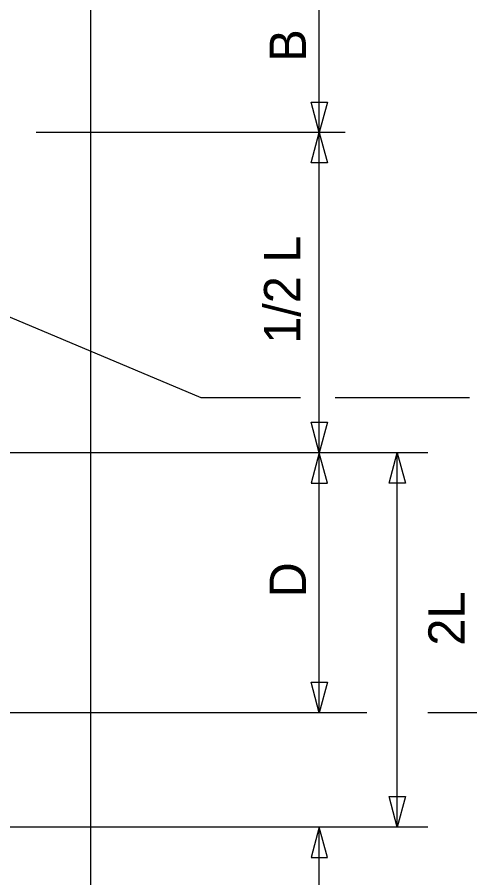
# Model space of a CAD drawing. Extents: x 16038 to 19504, y 5920 to 8321.
# Drawn here: x 17156.2 to 17243.3, y 7550.9 to 7716.4 of the extents above; entities that cross this region are included whole.
import ezdxf

# ---------------------------------------------------------------- set-up
doc = ezdxf.new("R2010")
doc.units = 0
doc.layers.add('PAVT_EDGE_EX', color=7, linetype='Continuous')
doc.layers.add('TYPICAL_TEXT_DIMEN_PR', color=7, linetype='Continuous')

msp = doc.modelspace()

# ---------------------------------------------------------------- linework, layer by layer
at = {"layer": 'PAVT_EDGE_EX'}
msp.add_line((17170.3, 8211.37), (17170.3, 7379.53), dxfattribs=at)
at = {"layer": 'TYPICAL_TEXT_DIMEN_PR'}
for p, q in [((17214.3, 7694.22), (17214.3, 7722.28)), ((17214.3, 7694.22), (17212.73, 7700.08)), ((17212.73, 7700.08), (17214.3, 7700.08)), ((17214.3, 7700.08), (17215.87, 7700.08)), ((17215.87, 7700.08), (17214.3, 7694.22)), ((17219.3, 7694.22), (17159.8, 7694.22)), ((17212.73, 7688.36), (17214.3, 7694.22)), ((17214.3, 7694.22), (17215.87, 7688.36)), ((17214.3, 7632.61), (17214.3, 7694.22)), ((17214.3, 7688.36), (17212.73, 7688.36)), ((17215.87, 7688.36), (17214.3, 7688.36)), ((17126.23, 7670.7), (17191.54, 7643.22)), ((17191.54, 7643.22), (17210.7, 7643.22)), ((17217.38, 7643.22), (17243.22, 7643.22)), ((17214.3, 7632.61), (17212.73, 7638.47)), ((17212.73, 7638.47), (17214.3, 7638.47)), ((17214.3, 7638.47), (17215.87, 7638.47)), ((17215.87, 7638.47), (17214.3, 7632.61)), ((17235.2, 7632.61), (17113.91, 7632.61)), ((17214.3, 7632.61), (17212.73, 7626.75)), ((17215.87, 7626.75), (17214.3, 7632.61)), ((17214.3, 7582.61), (17214.3, 7632.61)), ((17227.73, 7626.75), (17229.3, 7632.61)), ((17229.3, 7560.61), (17229.3, 7632.61)), ((17229.3, 7632.61), (17230.87, 7626.75)), ((17212.73, 7626.75), (17214.3, 7626.75)), ((17214.3, 7626.75), (17215.87, 7626.75)), ((17229.3, 7626.75), (17227.73, 7626.75)), ((17230.87, 7626.75), (17229.3, 7626.75)), ((17214.3, 7582.61), (17212.73, 7588.47)), ((17212.73, 7588.47), (17214.3, 7588.47)), ((17214.3, 7588.47), (17215.87, 7588.47)), ((17215.87, 7588.47), (17214.3, 7582.61)), ((17223.45, 7582.61), (17136.51, 7582.61)), ((17268.44, 7582.61), (17235.2, 7582.61)), ((17229.3, 7560.61), (17227.73, 7566.47)), ((17227.73, 7566.47), (17229.3, 7566.47)), ((17229.3, 7566.47), (17230.87, 7566.47)), ((17230.87, 7566.47), (17229.3, 7560.61)), ((17235.2, 7560.61), (17113.91, 7560.61)), ((17214.3, 7560.61), (17212.73, 7554.75)), ((17215.87, 7554.75), (17214.3, 7560.61)), ((17214.3, 7532.05), (17214.3, 7560.61)), ((17212.73, 7554.75), (17214.3, 7554.75)), ((17214.3, 7554.75), (17215.87, 7554.75))]:
    msp.add_line(p, q, dxfattribs=at)

# ---------------------------------------------------------------- texts
for s, p in [('B', (17211.74, 7707.84)), ('1/2 L', (17210.66, 7653.57)), ('D', (17211.74, 7604.79)), ('2L', (17242.29, 7595.51))]:
    msp.add_text(s, height=7, rotation=90, dxfattribs=at).set_placement(p)

doc.saveas('drawing.dxf')
